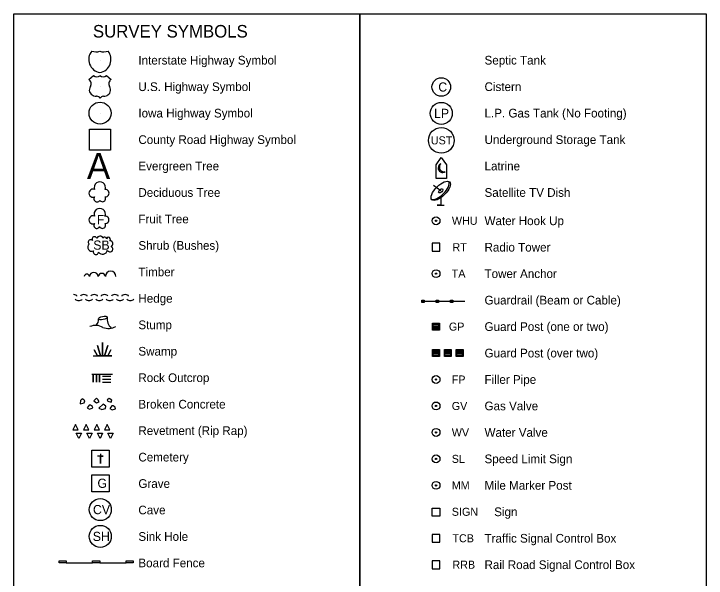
# Model space of a CAD drawing. Extents: x 6082259 to 6083454, y 5964102 to 5966092.
# Drawn here: x 6082259 to 6083454, y 5965119 to 5966092 of the extents above; entities that cross this region are included whole.
import ezdxf

# ---------------------------------------------------------------- set-up
doc = ezdxf.new("R2010")
doc.units = 0
for name, color, linetype in [('Default', 7, 'Continuous'), ('Level 22', 7, 'Continuous'), ('wetNoteSoil', 7, 'Continuous')]:
    doc.layers.add(name, color=color, linetype=linetype)

msp = doc.modelspace()

# ---------------------------------------------------------------- linework, layer by layer
at = {"layer": 'Default'}
for points in [[(6082259, 5966092.2), (6082856.5, 5966092.2), (6082856.5, 5964102.2), (6082259, 5964102.2)], [(6082856.5, 5966092.2), (6083454, 5966092.2), (6083454, 5964102.2), (6082856.5, 5964102.2)]]:
    msp.add_lwpolyline(points, close=True, dxfattribs=at)
at = {"layer": 'wetNoteSoil'}
for p, q in [((6082407.8, 5966012.2), (6082407.8, 5966012.2)), ((6082388.5, 5965978.8), (6082396.6, 5965986)), ((6082418.8, 5965985.9), (6082426.9, 5965978.7)), ((6082391, 5965966.7), (6082391.4, 5965967.3)), ((6082407.8, 5965966.5), (6082407.8, 5965966.5)), ((6082396.7, 5965951), (6082396, 5965951.3)), ((6082402.5, 5965950.1), (6082401.5, 5965950.1)), ((6082407.8, 5965920.9), (6082407.8, 5965920.9)), ((6082995.9, 5965786.9), (6082983.5, 5965796.2)), ((6082412.3, 5965467.3), (6082426.5, 5965467.3)), ((6082412.3, 5965462), (6082426.5, 5965462)), ((6082412.3, 5965456.6), (6082426.5, 5965456.6))]:
    msp.add_line(p, q, dxfattribs=at)
for points in [[(6082389.5, 5965893.5), (6082426, 5965893.5), (6082426, 5965857), (6082389.5, 5965857), (6082389.5, 5965893.5)], [(6082987.8, 5965808.3), (6082987.8, 5965831.8), (6082996.9, 5965844.5), (6083005.9, 5965831.8), (6083005.9, 5965808.3), (6082987.8, 5965808.3)], [(6082995.9, 5965774.5), (6082995.9, 5965762.1), (6082989.7, 5965762.1), (6083002.1, 5965762.1)], [(6082987.8, 5965682.8), (6082987.8, 5965682.8), (6082994.6, 5965682.8), (6082994.6, 5965696.4), (6082981, 5965696.4), (6082981, 5965682.8), (6082987.8, 5965682.8)], [(6082963.2, 5965594.3), (6082963.2, 5965598.4), (6082967.3, 5965598.4), (6082967.3, 5965594.3), (6082963.2, 5965594.3), (6082963.2, 5965595.7), (6082967.3, 5965595.7), (6082967.3, 5965597), (6082963.2, 5965597)], [(6082963.2, 5965596.4), (6083037.5, 5965596.4)], [(6082988, 5965594.3), (6082988, 5965598.4), (6082992.1, 5965598.4), (6082992.1, 5965594.3), (6082988, 5965594.3), (6082988, 5965595.7), (6082992.1, 5965595.7), (6082992.1, 5965597), (6082988, 5965597)], [(6083012.7, 5965594.3), (6083012.7, 5965598.4), (6083016.9, 5965598.4), (6083016.9, 5965594.3), (6083012.7, 5965594.3), (6083012.7, 5965595.7), (6083016.9, 5965595.7), (6083016.9, 5965597), (6083012.7, 5965597)], [(6082982.8, 5965547.7), (6082982.8, 5965557.6), (6082992.7, 5965557.6), (6082992.7, 5965547.7), (6082982.8, 5965547.7), (6082982.8, 5965549.7), (6082992.7, 5965549.7), (6082992.7, 5965551.7), (6082982.8, 5965551.7), (6082982.8, 5965553.7), (6082992.7, 5965553.7), (6082992.7, 5965555.6), (6082982.8, 5965555.6)], [(6082396, 5965502.1), (6082428.1, 5965502.1), (6082421, 5965502.1), (6082426.3, 5965512.8), (6082421, 5965502.1), (6082415.6, 5965502.1), (6082421, 5965520), (6082415.6, 5965502.1), (6082412.1, 5965502.1), (6082412.1, 5965525.3), (6082412.1, 5965502.1), (6082408.5, 5965502.1), (6082403.2, 5965520), (6082408.5, 5965502.1), (6082403.2, 5965502.1), (6082397.8, 5965512.8), (6082403.2, 5965502.1)], [(6082982.8, 5965502.1), (6082982.8, 5965512), (6082992.7, 5965512), (6082992.7, 5965502.1), (6082982.8, 5965502.1), (6082982.8, 5965504.1), (6082992.7, 5965504.1), (6082992.7, 5965506), (6082982.8, 5965506), (6082982.8, 5965508), (6082992.7, 5965508), (6082992.7, 5965510), (6082982.8, 5965510)], [(6083003.2, 5965502.1), (6083003.2, 5965512), (6083013.1, 5965512), (6083013.1, 5965502.1), (6083003.2, 5965502.1), (6083003.2, 5965504.1), (6083013.1, 5965504.1), (6083013.1, 5965506), (6083003.2, 5965506), (6083003.2, 5965508), (6083013.1, 5965508), (6083013.1, 5965510), (6083003.2, 5965510)], [(6083023.5, 5965502.1), (6083023.5, 5965512), (6083033.4, 5965512), (6083033.4, 5965502.1), (6083023.5, 5965502.1), (6083023.5, 5965504.1), (6083033.4, 5965504.1), (6083033.4, 5965506), (6083023.5, 5965506), (6083023.5, 5965508), (6083033.4, 5965508), (6083033.4, 5965510), (6083023.5, 5965510)], [(6082393.5, 5965470.9), (6082396.2, 5965470.9), (6082396.2, 5965456.6), (6082396.2, 5965470.9), (6082401.6, 5965470.9), (6082401.6, 5965456.6), (6082401.6, 5965470.9), (6082406.9, 5965470.9), (6082406.9, 5965456.6), (6082406.9, 5965470.9), (6082429.2, 5965470.9)], [(6082361, 5965374.6), (6082370.2, 5965374.6), (6082365.6, 5965383.8), (6082361, 5965374.6)], [(6082379.3, 5965374.6), (6082388.4, 5965374.6), (6082383.9, 5965383.8), (6082379.3, 5965374.6)], [(6082397.6, 5965374.6), (6082406.7, 5965374.6), (6082402.1, 5965383.8), (6082397.6, 5965374.6)], [(6082415.8, 5965374.6), (6082424.9, 5965374.6), (6082420.4, 5965383.8), (6082415.8, 5965374.6)], [(6082366.7, 5965368.6), (6082375.8, 5965368.6), (6082371.2, 5965359.5), (6082366.7, 5965368.6)], [(6082384.9, 5965368.6), (6082394.1, 5965368.6), (6082389.5, 5965359.5), (6082384.9, 5965368.6)], [(6082403.2, 5965368.6), (6082412.3, 5965368.6), (6082407.8, 5965359.5), (6082403.2, 5965368.6)], [(6082421.5, 5965368.6), (6082430.6, 5965368.6), (6082426, 5965359.5), (6082421.5, 5965368.6)], [(6082393.8, 5965310.2), (6082393.8, 5965339.7), (6082423.4, 5965339.7), (6082423.4, 5965310.2), (6082393.8, 5965310.2)], [(6082408.6, 5965333.3), (6082408.6, 5965316.6), (6082408.6, 5965328.9), (6082413.5, 5965328.9), (6082403.7, 5965328.9)], [(6082987.8, 5965180.8), (6082987.8, 5965180.8), (6082994.6, 5965180.8), (6082994.6, 5965194.3), (6082981, 5965194.3), (6082981, 5965180.8), (6082987.8, 5965180.8)], [(6082349.4, 5965145), (6082395, 5965145)], [(6082407.2, 5965145), (6082452.8, 5965145)], [(6082464.9, 5965145), (6082464.9, 5965145)], [(6082987.8, 5965135.1), (6082987.8, 5965135.1), (6082994.6, 5965135.1), (6082994.6, 5965148.7), (6082981, 5965148.7), (6082981, 5965135.1), (6082987.8, 5965135.1)]]:
    msp.add_lwpolyline(points, dxfattribs=at)
for points in [[(6082981.8, 5965546.7), (6082981.8, 5965558.6), (6082993.7, 5965558.6), (6082993.7, 5965546.7)], [(6082981.8, 5965501.1), (6082981.8, 5965513), (6082993.7, 5965513), (6082993.7, 5965501.1)], [(6083002.2, 5965501.1), (6083002.2, 5965513), (6083014.1, 5965513), (6083014.1, 5965501.1)], [(6083022.5, 5965501.1), (6083022.5, 5965513), (6083034.4, 5965513), (6083034.4, 5965501.1)], [(6082401.7, 5965429), (6082397.3, 5965424.9), (6082401.5, 5965421.3), (6082406.4, 5965422.8), (6082404.3, 5965427.2)], [(6082423.7, 5965428.6), (6082419.9, 5965426.3), (6082421.1, 5965424.2), (6082427.1, 5965422.6), (6082427.9, 5965425.5)], [(6082376.8, 5965427.8), (6082374.2, 5965425.4), (6082373.7, 5965419.7), (6082380.2, 5965421.3), (6082381.5, 5965424.9), (6082379.7, 5965426.2)], [(6082389.2, 5965417.2), (6082385.6, 5965412.5), (6082389.8, 5965410.4), (6082395.5, 5965412.3), (6082394.9, 5965415.1), (6082391.3, 5965417.2)], [(6082413.2, 5965419), (6082406, 5965411.8), (6082410.9, 5965409.4), (6082417.4, 5965411.3), (6082417.6, 5965415.4)], [(6082428.2, 5965416), (6082424.6, 5965411.4), (6082428.7, 5965409.3), (6082434.4, 5965411.1), (6082433.9, 5965413.9), (6082430.3, 5965416)], [(6082393.7, 5965267.5), (6082393.7, 5965297.2), (6082423.5, 5965297.2), (6082423.5, 5965267.5)], [(6082981, 5965225.7), (6082981, 5965239.2), (6082994.6, 5965239.2), (6082994.6, 5965225.7)], [(6082337.2, 5965145), (6082337.2, 5965148.4), (6082349.4, 5965148.4), (6082349.4, 5965145)], [(6082395, 5965145), (6082395, 5965148.4), (6082407.2, 5965148.4), (6082407.2, 5965145)], [(6082452.8, 5965145), (6082452.8, 5965148.4), (6082464.9, 5965148.4), (6082464.9, 5965145)]]:
    msp.add_lwpolyline(points, close=True, dxfattribs=at)
for centre, radius in [((6082996.8, 5965966), 16), ((6082407.8, 5965920.9), 19), ((6082996.9, 5965920.5), 19), ((6082996.9, 5965873.9), 22.2), ((6082987.8, 5965735.2), 6.79), ((6082987.8, 5965735.2), 1.13), ((6082987.8, 5965644), 6.79), ((6082987.8, 5965644), 1.13), ((6082987.8, 5965461.4), 6.79), ((6082987.8, 5965461.4), 1.13), ((6082987.8, 5965415.8), 6.79), ((6082987.8, 5965415.8), 1.13), ((6082987.8, 5965370.1), 6.79), ((6082987.8, 5965370.1), 1.13), ((6082987.8, 5965324.5), 6.79), ((6082987.8, 5965324.5), 1.13), ((6082987.8, 5965278.8), 6.79), ((6082987.8, 5965278.8), 1.13), ((6082408.2, 5965237), 19), ((6082408.2, 5965190.7), 19)]:
    msp.add_circle(centre, radius, dxfattribs=at)
for centre, radius, start, end in [((6082411.4, 5966013.6), 23, 141.2897, 260.377), ((6082401.1, 5966050), 23.3, 250.8344, 286.0898), ((6082414, 5966050), 23.3, 253.9102, 289.1613), ((6082403.7, 5966013.6), 23, 279.623, 38.7204), ((6082414, 5966050), 23.3, 289.1818, 289.185), ((6082384.1, 5965971.6), 8.46, 328.1178, 58.4185), ((6082402.4, 5965992.1), 8.46, 226.652, 308.6604), ((6082413, 5965992.1), 8.46, 230.5703, 313.348), ((6082431.3, 5965971.5), 8.46, 121.5815, 211.8822), ((6082399.6, 5965961), 10.3, 145.8972, 250.3585), ((6082415.8, 5965960.9), 10.3, 289.6415, 34.1028), ((6082403.5, 5965974.1), 24.1, 253.4797, 265.7777), ((6082402.1, 5965943), 7.07, 33.6844, 87.4407), ((6082413.9, 5965942.9), 7.07, 95.8567, 146.3156), ((6082411.9, 5965974.1), 24.1, 274.6642, 286.5203), ((6082999.3, 5965826.4), 7.87, 116.2289, 304.7925), ((6083001.5, 5965827.5), 7.91, 142.8907, 286.2253), ((6082407.5, 5965792.7), 9.75, 338.2051, 201.7949), ((6082395.5, 5965782.8), 6.97, 65.4824, 294.5175), ((6082417, 5965782.8), 6.36, 265.9982, 94.0018), ((6082402.6, 5965773.2), 5.31, 142.7501, 335.3223), ((6082412.2, 5965773.4), 5.3, 206.5242, 35.4033), ((6082407.3, 5965746.8), 9.75, 338.2051, 201.7949), ((6082395.4, 5965736.8), 6.97, 65.4824, 294.5175), ((6082416.8, 5965736.8), 6.36, 265.9982, 94.0018), ((6082402.5, 5965727.3), 5.31, 142.7501, 335.3223), ((6082412.1, 5965727.4), 5.3, 206.5242, 35.4033), ((6082398.1, 5965703.7), 4.12, 10.5948, 214.3611), ((6082407.6, 5965703.1), 5.57, 22.6036, 165.7836), ((6082415.7, 5965704.1), 3.15, 0.4605, 158.7839), ((6082422.3, 5965703.3), 3.57, 311.3936, 166.4114), ((6082393.2, 5965689.4), 6.62, 125.8289, 299.2848), ((6082391.7, 5965698.3), 4.32, 45.3455, 236.8073), ((6082425, 5965695.5), 5.15, 290.9039, 94.3687), ((6082400.8, 5965681.8), 4.68, 157.0258, 349.7602), ((6082412.2, 5965686.7), 8.99, 220.0183, 343.6977), ((6082425.2, 5965686.2), 4.79, 204.8294, 69.8871), ((6082397.2, 5965638.4), 7.66, 5.6097, 174.3903), ((6082410.9, 5965638.4), 6.15, 6.8184, 173.1816), ((6082426.2, 5965639.2), 9.15, 0, 180), ((6082385, 5965638.5), 4.63, 8.8069, 171.1931), ((6082388.6, 5965565.5), 16.7, 319.4836, 1.8241), ((6082444, 5965567.1), 24, 175.4776, 225.2691), ((6082400.1, 5965530.5), 24.2, 58.6739, 113.6979), ((6082422.1, 5965578.6), 29, 251.1942, 296.4339)]:
    msp.add_arc(centre, radius, start, end, dxfattribs=at)
for centre, major_axis, ratio in [((6082995.9, 5965786.9), (-15.3, -15.3), 0.428571), ((6082995.9, 5965786.9), (-3.28, -3.28), 0.5), ((6082412.7, 5965567.5), (-7.43, -1.49), 0.385758)]:
    msp.add_ellipse(centre, major_axis=major_axis, ratio=ratio, dxfattribs=at)
for centre, major_axis, ratio, start_param, end_param in [((6082994.1, 5965788.6), (-15.3, -15.3), 0.428571, 0.159141, 2.993624), ((6082362.1, 5965605.4), (5.94, 0), 0.4, 0, 1.570796), ((6082379.9, 5965605.4), (-5.94, 0), 0.4, 4.712389, 6.283185), ((6082379.9, 5965605.4), (5.94, 0), 0.4, 0, 1.570796), ((6082397.7, 5965605.4), (-5.94, 0), 0.4, 4.712389, 6.283185), ((6082397.7, 5965605.4), (5.94, 0), 0.4, 0, 1.570796), ((6082415.5, 5965605.4), (-5.94, 0), 0.4, 4.712389, 6.283185), ((6082415.5, 5965605.4), (5.94, 0), 0.4, 0, 1.570796), ((6082433.4, 5965605.4), (-5.94, 0), 0.4, 4.712389, 6.283185), ((6082433.4, 5965605.4), (5.94, 0), 0.4, 0, 1.570796), ((6082451.2, 5965605.4), (-5.94, 0), 0.4, 4.712389, 6.283185), ((6082451.2, 5965605.4), (5.94, 0), 0.4, 0, 1.570796), ((6082371, 5965600.1), (-5.94, 0), 0.4, 0, 3.141593), ((6082388.8, 5965600.1), (-5.94, 0), 0.4, 0, 3.141593), ((6082406.6, 5965600.1), (-5.94, 0), 0.4, 0, 3.141593), ((6082424.5, 5965600.1), (-5.94, 0), 0.4, 0, 3.141593), ((6082442.3, 5965600.1), (-5.94, 0), 0.4, 0, 3.141593), ((6082460.1, 5965600.1), (-5.94, 0), 0.4, 0, 3.141593)]:
    msp.add_ellipse(centre, major_axis=major_axis, ratio=ratio, start_param=start_param, end_param=end_param, dxfattribs=at)

# ---------------------------------------------------------------- texts
at = {"layer": 'Level 22'}
for s, height, p in [('SURVEY SYMBOLS', 21.667, (6082395.5, 5966051.3)), ('Interstate Highway Symbol', 15, (6082474, 5966004.7)), ('Septic Tank', 15, (6083071.5, 5966004.7)), ('U.S. Highway Symbol', 15, (6082474, 5965959)), ('Cistern', 15, (6083071.5, 5965959)), ('Iowa Highway Symbol', 15, (6082474, 5965913.4)), ('L.P. Gas Tank (No Footing)', 15, (6083071.5, 5965913.4)), ('County Road Highway Symbol', 15, (6082474, 5965867.7)), ('Underground Storage Tank', 15, (6083071.5, 5965867.7)), ('Evergreen Tree', 15, (6082474, 5965822.1)), ('Latrine', 15, (6083071.5, 5965822.1)), ('Deciduous Tree', 15, (6082474, 5965776.5)), ('Satellite TV Dish', 15, (6083071.5, 5965776.5)), ('Fruit Tree', 15, (6082474, 5965730.8)), ('Water Hook Up', 15, (6083071.5, 5965727.7)), ('Shrub (Bushes)', 15, (6082474, 5965685.2)), ('Radio Tower', 15, (6083071.5, 5965682.1)), ('Timber', 15, (6082474, 5965639.5)), ('Tower Anchor', 15, (6083071.5, 5965636.5)), ('Hedge', 15, (6082474, 5965593.9)), ('Guardrail (Beam or Cable)', 15, (6083071.5, 5965590.8)), ('Stump', 15, (6082474, 5965548.2)), ('Guard Post (one or two)', 15, (6083071.5, 5965545.2)), ('Swamp', 15, (6082474, 5965502.6)), ('Guard Post (over two)', 15, (6083071.5, 5965499.5)), ('Rock Outcrop', 15, (6082474, 5965457)), ('Filler Pipe', 15, (6083071.5, 5965453.9)), ('Broken Concrete', 15, (6082474, 5965411.3)), ('Gas Valve', 15, (6083071.5, 5965408.3)), ('Revetment (Rip Rap)', 15, (6082474, 5965365.7)), ('Water Valve', 15, (6083071.5, 5965362.6)), ('Cemetery', 15, (6082474, 5965320)), ('Speed Limit Sign', 15, (6083071.5, 5965317)), ('Grave', 15, (6082474, 5965274.4)), ('Mile Marker Post', 15, (6083071.5, 5965271.3)), ('Sink Hole', 15, (6082474, 5965183.1)), ('Traffic Signal Control Box', 15, (6083071.5, 5965180)), ('Board Fence', 15, (6082474, 5965137.5)), ('Rail Road Signal Control Box', 15, (6083071.5, 5965134.4))]:
    msp.add_text(s, height=height, dxfattribs=at).set_placement(p)
at = {"layer": 'wetNoteSoil'}
for s, height, p in [('C', 15.8, (6082991.7, 5965958.1)), ('LP', 15.85, (6082984.3, 5965912.5)), ('UST', 13.87, (6082978.8, 5965867)), ('A', 45.3, (6082385.1, 5965807)), ('F', 15.8, (6082402.3, 5965729.3)), ('WHU', 13.82, (6083015.2, 5965728.3)), ('SB', 15.85, (6082396.1, 5965685.3)), ('RT', 13.87, (6083016.1, 5965682.7)), ('TA', 13.93, (6083014.8, 5965637.2)), ('GP', 13.87, (6083010, 5965545.7)), ('FP', 13.82, (6083015, 5965454.5)), ('GV', 13.82, (6083015, 5965408.8)), ('WV', 13.82, (6083015, 5965363.2)), ('SL', 13.82, (6083015, 5965317.6)), ('G', 15.8, (6082403.4, 5965274.5)), ('MM', 13.82, (6083015, 5965271.9)), ('CV', 15.85, (6082395.6, 5965229.1)), ('Cave', 15, (6082474, 5965228.8)), ('SIGN', 13.87, (6083015, 5965226.3)), ('Sign', 15, (6083088.2, 5965225.7)), ('SH', 15.85, (6082395.3, 5965182.8)), ('TCB', 13.87, (6083016.1, 5965180.6)), ('RRB', 13.87, (6083016.1, 5965135))]:
    msp.add_text(s, height=height, dxfattribs=at).set_placement(p)

doc.saveas('drawing.dxf')
